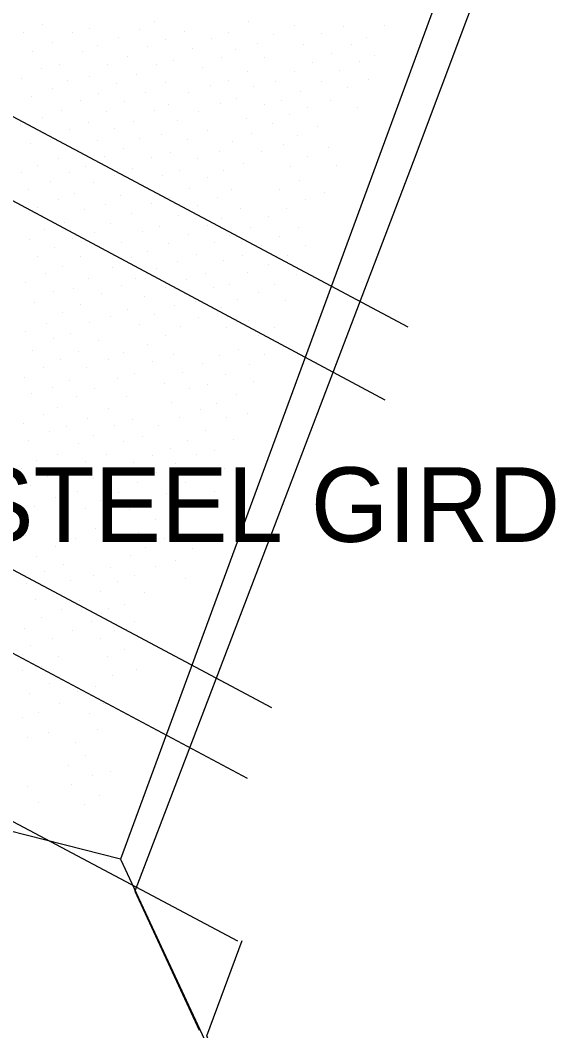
# Model space of a CAD drawing. Extents: x 1729983 to 1730242, y 468641 to 469019.
# Drawn here: x 1730124.77 to 1730137.55, y 468724.33 to 468748.72 of the extents above; entities that cross this region are included whole.
import ezdxf

# ---------------------------------------------------------------- set-up
doc = ezdxf.new("R2010")
doc.units = 0
for name, color, linetype in [('Default', 7, 'Continuous'), ('S_Bridge_Abutment_Bottom', 7, 'Continuous'), ('S_Ground_SpotElevation', 7, 'Continuous'), ('S_Misc_MiscFeature', 7, 'Continuous'), ('S_Roadway_Sidewalks', 7, 'Continuous'), ('S_Text', 7, 'Continuous')]:
    doc.layers.add(name, color=color, linetype=linetype)

# ---------------------------------------------------------------- blocks, each defined once
blk = doc.blocks.new('POINT_DISPLAY')
at = {"layer": 'Default'}
blk.add_line((0, 0), (0, 0), dxfattribs=at)

msp = doc.modelspace()

# ---------------------------------------------------------------- linework, layer by layer
at = {"layer": 'S_Bridge_Abutment_Bottom'}
msp.add_lwpolyline([(1730181.425, 468864.71), (1730176.506, 468862.351), (1730175.427, 468859.495), (1730170.121, 468844.945), (1730162.576, 468824.377), (1730156.015, 468806.678), (1730146.892, 468781.991), (1730136.8, 468754.596), (1730127.192, 468728.47), (1730129.433, 468723.646)], dxfattribs=at)
at = {"layer": 'S_Misc_MiscFeature'}
for p, q in [((1730134.131, 468741.31), (1730106.222, 468756.158)), ((1730105.571, 468754.535), (1730133.572, 468739.555)), ((1730102.847, 468747.037), (1730130.837, 468732.131)), ((1730130.252, 468730.415), (1730102.19, 468745.399)), ((1730130.021, 468726.489), (1730100.897, 468741.974))]:
    msp.add_line(p, q, dxfattribs=at)
for points in [[(1730180.75, 468864.535), (1730177.366, 468862.873), (1730174.461, 468854.957), (1730171.273, 468846.168), (1730167.811, 468836.657), (1730164.365, 468827.147), (1730154.502, 468800.309), (1730151.107, 468790.853), (1730144.524, 468772.905), (1730140.96, 468763.264), (1730137.54, 468754.064), (1730134.249, 468745.295), (1730130.903, 468736.495), (1730127.535, 468727.691), (1730129.089, 468724.341)], [(1730129.157, 468723.271), (1730129.518, 468723.611), (1730129.273, 468724.207), (1730130.126, 468726.505)]]:
    msp.add_lwpolyline(points, dxfattribs=at)
at = {"layer": 'S_Roadway_Sidewalks'}
msp.add_lwpolyline([(1730127.192, 468728.47), (1730122.195, 468729.739), (1730112.887, 468731.671)], dxfattribs=at)

# ---------------------------------------------------------------- block references
at = {"layer": 'S_Ground_SpotElevation'}
for p in [(1730128.009, 468748.685), (1730125.316, 468748.608), (1730126.443, 468748.524), (1730127.644, 468748.501), (1730128.741, 468748.444), (1730130.269, 468748.68), (1730131.385, 468748.59), (1730132.57, 468748.553), (1730133.57, 468748.584), (1730124.855, 468748.411), (1730126.034, 468748.407), (1730127.144, 468748.297), (1730128.279, 468748.257), (1730129.38, 468748.263), (1730129.799, 468748.418), (1730130.876, 468748.369), (1730132.047, 468748.395), (1730133.126, 468748.287), (1730125.061, 468747.952), (1730125.547, 468748.186), (1730126.271, 468747.955), (1730126.64, 468748.108), (1730127.851, 468748.072), (1730128.94, 468748.026), (1730129.978, 468748.02), (1730130.489, 468748.151), (1730131.602, 468748.135), (1730132.76, 468748.132), (1730127.366, 468747.844), (1730128.478, 468747.751), (1730129.621, 468747.817), (1730130.678, 468747.821), (1730132.283, 468747.921), (1730132.952, 468747.722), (1730133.318, 468747.871), (1730125.284, 468747.544), (1730125.715, 468747.635), (1730126.87, 468747.646), (1730128.052, 468747.652), (1730129.169, 468747.563), (1730130.256, 468747.467), (1730131.379, 468747.474), (1730131.819, 468747.683), (1730132.47, 468747.509), (1730124.8, 468747.304), (1730125.92, 468747.25), (1730126.454, 468747.363), (1730127.585, 468747.406), (1730129.788, 468747.259), (1730130.934, 468747.248), (1730132.043, 468747.226), (1730133.163, 468747.285), (1730125.55, 468747.068), (1730127.092, 468747.188), (1730128.279, 468747.201), (1730129.375, 468747.137), (1730130.41, 468747.126), (1730131.53, 468747), (1730132.672, 468747.087), (1730125.034, 468746.874), (1730126.221, 468746.766), (1730126.651, 468746.94), (1730127.299, 468746.763), (1730127.804, 468746.96), (1730128.835, 468746.962), (1730129.99, 468746.831), (1730131.076, 468746.773), (1730132.263, 468746.767), (1730125.775, 468746.537), (1730126.85, 468746.517), (1730128.012, 468746.541), (1730128.349, 468746.686), (1730129.063, 468746.51), (1730129.596, 468746.695), (1730130.661, 468746.683), (1730131.71, 468746.616), (1730132.907, 468746.614), (1730125.31, 468746.376), (1730126.42, 468746.256), (1730127.502, 468746.259), (1730128.575, 468746.287), (1730130.238, 468746.35), (1730131.274, 468746.439), (1730124.785, 468746.188), (1730125.971, 468746.072), (1730127.049, 468746.103), (1730129.297, 468746.058), (1730130.853, 468746.23), (1730131.94, 468746.144), (1730125.515, 468745.84), (1730126.633, 468745.81), (1730127.653, 468745.85), (1730128.19, 468745.968), (1730128.804, 468745.836), (1730129.886, 468745.779), (1730130.355, 468745.983), (1730131.455, 468745.921), (1730125.029, 468745.73), (1730126.168, 468745.59), (1730127.261, 468745.62), (1730128.387, 468745.518), (1730129.579, 468745.541), (1730130.586, 468745.551), (1730131.13, 468745.71), (1730132.203, 468745.638), (1730125.699, 468745.376), (1730126.809, 468745.428), (1730127.951, 468745.411), (1730129.038, 468745.384), (1730131.702, 468745.432), (1730124.795, 468745.037), (1730125.184, 468745.212), (1730125.973, 468745.042), (1730126.351, 468745.19), (1730127.491, 468745.132), (1730128.625, 468745.09), (1730129.686, 468745.079), (1730130.162, 468745.262), (1730131.305, 468745.192), (1730132.4, 468745.206), (1730125.5, 468744.814), (1730126.536, 468744.79), (1730127.052, 468744.976), (1730128.199, 468744.97), (1730129.287, 468744.917), (1730131.522, 468744.851), (1730124.978, 468744.637), (1730126.073, 468744.537), (1730127.709, 468744.724), (1730128.846, 468744.653), (1730129.882, 468744.621), (1730131.03, 468744.64), (1730132.103, 468744.565), (1730125.7, 468744.39), (1730127.189, 468744.48), (1730128.374, 468744.43), (1730129.544, 468744.43), (1730131.648, 468744.389), (1730125.183, 468744.195), (1730126.32, 468744.138), (1730126.84, 468744.27), (1730127.946, 468744.283), (1730129.056, 468744.235), (1730130.086, 468744.164), (1730131.193, 468744.164), (1730125.846, 468743.834), (1730127.455, 468744.039), (1730128.585, 468744.009), (1730129.636, 468743.937), (1730130.758, 468743.974), (1730125.371, 468743.671), (1730126.577, 468743.594), (1730126.956, 468743.798), (1730127.724, 468743.604), (1730128.137, 468743.748), (1730129.299, 468743.768), (1730130.326, 468743.715), (1730131.487, 468743.707), (1730125.003, 468743.413), (1730126.032, 468743.437), (1730127.214, 468743.359), (1730128.342, 468743.335), (1730128.834, 468743.538), (1730129.47, 468743.347), (1730129.83, 468743.522), (1730131.036, 468743.501), (1730125.591, 468743.225), (1730126.779, 468743.176), (1730127.854, 468743.122), (1730130.596, 468743.274), (1730131.653, 468743.28), (1730125.189, 468743.008), (1730126.228, 468743.022), (1730127.447, 468742.996), (1730128.565, 468742.901), (1730129.032, 468743.055), (1730129.687, 468742.922), (1730130.144, 468743.047), (1730131.225, 468743.037), (1730125.387, 468742.594), (1730125.8, 468742.776), (1730126.996, 468742.745), (1730128.054, 468742.713), (1730129.235, 468742.595), (1730130.256, 468742.627), (1730130.764, 468742.809), (1730131.44, 468742.589), (1730124.899, 468742.382), (1730126.43, 468742.479), (1730127.564, 468742.491), (1730128.796, 468742.447), (1730129.827, 468742.343), (1730130.915, 468742.345), (1730125.585, 468742.173), (1730126.052, 468742.236), (1730126.736, 468742.116), (1730127.216, 468742.303), (1730128.277, 468742.274), (1730129.437, 468742.263), (1730130.52, 468742.139), (1730125.122, 468741.914), (1730126.229, 468741.855), (1730127.782, 468742.059), (1730128.99, 468741.928), (1730130.014, 468741.964), (1730131.171, 468741.957), (1730125.782, 468741.662), (1730127.373, 468741.742), (1730128.49, 468741.837), (1730129.639, 468741.793), (1730125.407, 468741.403), (1730126.443, 468741.426), (1730126.955, 468741.56), (1730128.02, 468741.604), (1730129.071, 468741.53), (1730130.284, 468741.464), (1730124.901, 468741.193), (1730125.977, 468741.165), (1730127.649, 468741.362), (1730128.647, 468741.318), (1730129.754, 468741.307), (1730130.915, 468741.305), (1730125.574, 468741.027), (1730126.663, 468740.979), (1730127.851, 468740.887), (1730128.287, 468741.098), (1730130.518, 468741.094), (1730125.076, 468740.745), (1730126.191, 468740.724), (1730127.254, 468740.702), (1730128.464, 468740.637), (1730130.043, 468740.775), (1730130.663, 468740.646), (1730125.734, 468740.523), (1730126.893, 468740.523), (1730127.963, 468740.483), (1730129.178, 468740.434), (1730129.588, 468740.622), (1730130.296, 468740.403), (1730125.334, 468740.337), (1730126.372, 468740.323), (1730127.526, 468740.191), (1730128.695, 468740.223), (1730129.73, 468740.175), (1730124.873, 468740.085), (1730125.969, 468740.008), (1730127.111, 468740.077), (1730128.253, 468739.946), (1730129.296, 468739.923), (1730130.396, 468739.991), (1730125.044, 468739.7), (1730125.564, 468739.849), (1730126.556, 468739.824), (1730128.85, 468739.829), (1730129.988, 468739.692), (1730126.127, 468739.642), (1730127.336, 468739.623), (1730128.43, 468739.492), (1730129.515, 468739.466), (1730125.328, 468739.197), (1730125.677, 468739.379), (1730126.904, 468739.337), (1730129.121, 468739.327), (1730130.255, 468739.222), (1730124.853, 468738.977), (1730126.399, 468739.094), (1730127.047, 468738.943), (1730127.471, 468739.077), (1730128.62, 468739.122), (1730129.742, 468739.126), (1730125.472, 468738.796), (1730125.879, 468738.919), (1730126.534, 468738.698), (1730128.113, 468738.925), (1730129.254, 468738.802), (1730124.964, 468738.578), (1730126.169, 468738.49), (1730127.255, 468738.54), (1730127.729, 468738.671), (1730128.819, 468738.58), (1730129.928, 468738.598), (1730125.679, 468738.235), (1730126.863, 468738.228), (1730127.972, 468738.211), (1730128.401, 468738.382), (1730129.034, 468738.245), (1730129.463, 468738.342), (1730125.157, 468738.081), (1730126.347, 468738.053), (1730127.496, 468738.046), (1730128.519, 468738.013), (1730124.794, 468737.898), (1730125.856, 468737.849), (1730127.079, 468737.788), (1730128.063, 468737.789), (1730129.261, 468737.805), (1730129.693, 468737.904), (1730125.01, 468737.488), (1730125.434, 468737.697), (1730126.536, 468737.648), (1730127.608, 468737.567), (1730128.767, 468737.556), (1730126.145, 468737.342), (1730127.154, 468737.319), (1730128.311, 468737.301), (1730129.463, 468737.347), (1730125.128, 468736.98), (1730125.613, 468737.185), (1730126.701, 468737.128), (1730127.924, 468737.135), (1730126.345, 468736.923), (1730127.399, 468736.905), (1730128.571, 468736.801), (1730125.866, 468736.646), (1730126.95, 468736.68), (1730128.029, 468736.663), (1730124.895, 468736.286), (1730126.585, 468736.443), (1730127.222, 468736.265), (1730127.63, 468736.363), (1730125.624, 468736.01), (1730126.119, 468736.217), (1730128.256, 468736.204), (1730125.171, 468735.781), (1730127.443, 468735.806), (1730127.804, 468735.978), (1730128.929, 468735.974), (1730125.814, 468735.591), (1730126.946, 468735.513), (1730128.042, 468735.529), (1730128.531, 468735.684), (1730125.37, 468735.419), (1730126.538, 468735.321), (1730127.538, 468735.313), (1730124.919, 468735.11), (1730125.983, 468735.199), (1730127.113, 468735.171), (1730128.752, 468735.242), (1730126.712, 468734.93), (1730127.782, 468734.905), (1730125.144, 468734.745), (1730126.209, 468734.712), (1730127.301, 468734.609), (1730125.281, 468734.307), (1730125.769, 468734.491), (1730126.903, 468734.508), (1730126.487, 468734.195), (1730127.526, 468734.214), (1730124.879, 468734.045), (1730126.037, 468733.993), (1730127.039, 468733.977), (1730125.024, 468733.628), (1730125.549, 468733.802), (1730126.705, 468733.802), (1730125.686, 468733.348), (1730126.89, 468733.355), (1730127.283, 468733.535), (1730125.279, 468733.128), (1730124.839, 468733.013), (1730127.009, 468732.911), (1730127.574, 468733.033), (1730125.483, 468732.705), (1730126.578, 468732.623), (1730125.007, 468732.469), (1730126.158, 468732.513), (1730125.719, 468732.236), (1730126.787, 468732.218), (1730124.827, 468731.875), (1730125.225, 468732.012), (1730126.441, 468731.988), (1730124.944, 468731.403), (1730125.463, 468731.534), (1730126.628, 468731.605), (1730126.116, 468731.284), (1730126.354, 468730.959), (1730125.934, 468730.719), (1730126.519, 468730.477), (1730126.961, 468730.578), (1730124.94, 468730.226), (1730126.021, 468730.265), (1730126.681, 468729.993), (1730125.209, 468729.833), (1730126.324, 468729.783)]:
    msp.add_blockref('POINT_DISPLAY', p, dxfattribs=at)

# ---------------------------------------------------------------- texts
at = {"layer": 'S_Text'}
msp.add_text('BOT STEEL GIRDER', height=1.8, dxfattribs=at).set_placement((1730117.872, 468736.125))

doc.saveas('drawing.dxf')
